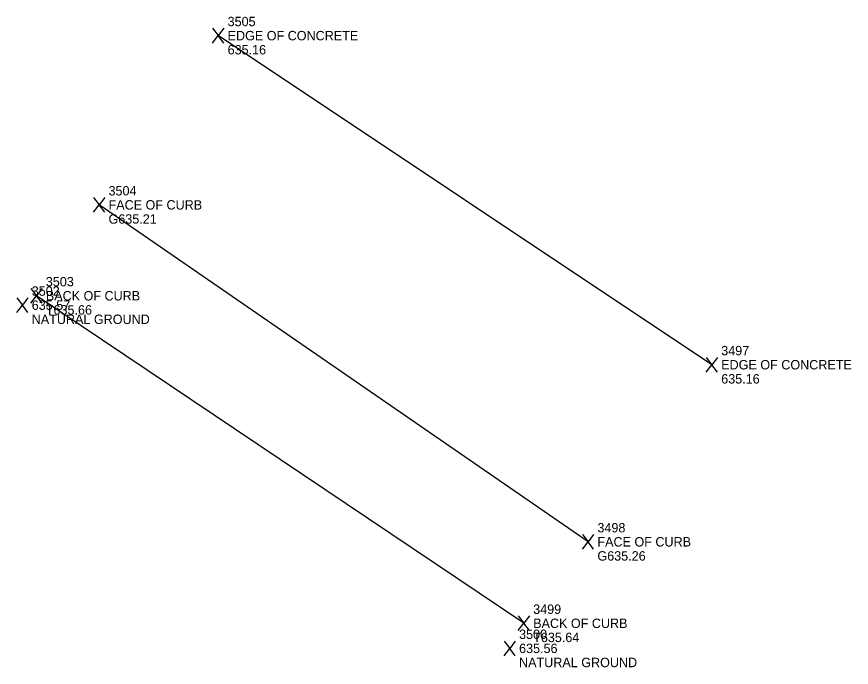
# Model space of a CAD drawing. Extents: x 2250985 to 2256614, y 13788366 to 13792478.
# Drawn here: x 2255030.8 to 2255036.13, y 13790711.88 to 13790716.03 of the extents above; entities that cross this region are included whole.
import ezdxf

# ---------------------------------------------------------------- set-up
doc = ezdxf.new("R2010")
doc.units = 0
for name, color, linetype in [('BORD_legend_drn_area', 7, 'Continuous'), ('BORD_legend_int', 7, 'Continuous'), ('BORD_legend_plan_prof_screen', 7, 'Continuous'), ('BORD_legend_TCP', 7, 'Continuous'), ('BORD_legend_TCP_screen', 7, 'Continuous'), ('BORD_notes_SAWS_sewer', 7, 'Continuous'), ('BORD_notes_SAWS_sewer_prof', 7, 'Continuous'), ('BORD_scale_plan_400', 7, 'Continuous'), ('BORD_scale_plan_profile_100_10', 7, 'Continuous'), ('BORD_scale_plan_profile_10_5', 7, 'Continuous'), ('BORD_scale_plan_profile_20_2', 7, 'Continuous'), ('BORD_scale_plan_profile_40_10', 7, 'Continuous'), ('BORD_seal_BA', 7, 'Continuous'), ('E_Road_Unpaved', 7, 'Continuous'), ('E_ROW_Driveway', 7, 'Continuous'), ('E_ROW_PropertyLine', 7, 'Continuous')]:
    doc.layers.add(name, color=color, linetype=linetype)

# ---------------------------------------------------------------- blocks, each defined once
blk = doc.blocks.new('EC')
at = {"layer": 'BORD_notes_SAWS_sewer'}
for p in [(-0.072, 0.094), (-0.072, -0.094), (0.072, 0.094), (0.072, -0.094)]:
    blk.add_line(p, (0, 0), dxfattribs=at)
blk = doc.blocks.new('CRB')
at = {"layer": 'BORD_scale_plan_400'}
for p in [(-0.072, 0.094), (-0.072, -0.094), (0.072, 0.094), (0.072, -0.094)]:
    blk.add_line(p, (0, 0), dxfattribs=at)
blk = doc.blocks.new('NG')
at = {"layer": 'BORD_legend_plan_prof_screen'}
for p in [(-0.072, 0.094), (-0.072, -0.094), (0.072, 0.094), (0.072, -0.094)]:
    blk.add_line(p, (0, 0), dxfattribs=at)
blk = doc.blocks.new('GUT')
at = {"layer": 'BORD_seal_BA'}
for p in [(-0.072, 0.094), (-0.072, -0.094), (0.072, 0.094), (0.072, -0.094)]:
    blk.add_line(p, (0, 0), dxfattribs=at)

msp = doc.modelspace()

# ---------------------------------------------------------------- linework, layer by layer
at = {"layer": 'BORD_seal_BA'}
for p in [(2255034.414, 13790712.727), (2255034.486, 13790712.727), (2255034.414, 13790712.633), (2255034.486, 13790712.633)]:
    msp.add_line(p, (2255034.45, 13790712.68), dxfattribs=at)
at = {"layer": 'E_Road_Unpaved'}
msp.add_line((2255034.04, 13790712.16), (2255030.93, 13790714.25), dxfattribs=at)
at = {"layer": 'E_ROW_Driveway'}
msp.add_line((2255035.24, 13790713.81), (2255032.09, 13790715.91), dxfattribs=at)
at = {"layer": 'E_ROW_PropertyLine'}
msp.add_line((2255034.45, 13790712.68), (2255031.33, 13790714.83), dxfattribs=at)

# ---------------------------------------------------------------- block references
at = {"layer": 'BORD_legend_plan_prof_screen', "xscale": 0.5, "yscale": 0.5}
for p in [(2255030.84, 13790714.19), (2255033.95, 13790712)]:
    msp.add_blockref('NG', p, dxfattribs=at)
at = {"layer": 'BORD_notes_SAWS_sewer', "xscale": 0.5, "yscale": 0.5}
for p in [(2255032.09, 13790715.91), (2255035.24, 13790713.81)]:
    msp.add_blockref('EC', p, dxfattribs=at)
at = {"layer": 'BORD_scale_plan_400', "xscale": 0.5, "yscale": 0.5}
for p in [(2255030.93, 13790714.25), (2255034.04, 13790712.16)]:
    msp.add_blockref('CRB', p, dxfattribs=at)
at = {"layer": 'BORD_seal_BA', "xscale": 0.5, "yscale": 0.5}
msp.add_blockref('GUT', (2255031.33, 13790714.83), dxfattribs=at)

# ---------------------------------------------------------------- texts
at = {"layer": 'BORD_legend_drn_area'}
for p in [(2255032.15, 13790715.88), (2255035.3, 13790713.78)]:
    msp.add_text('EDGE OF CONCRETE', height=0.06, dxfattribs=at).set_placement(p)
at = {"layer": 'BORD_legend_int'}
for p in [(2255030.9, 13790714.07), (2255034.01, 13790711.88)]:
    msp.add_text('NATURAL GROUND', height=0.06, dxfattribs=at).set_placement(p)
at = {"layer": 'BORD_legend_TCP'}
for s, p in [('3502', (2255030.9, 13790714.25)), ('3500', (2255034.01, 13790712.06))]:
    msp.add_text(s, height=0.06, dxfattribs=at).set_placement(p)
at = {"layer": 'BORD_legend_TCP_screen'}
for s, p in [('635.57', (2255030.9, 13790714.16)), ('635.56', (2255034.01, 13790711.97))]:
    msp.add_text(s, height=0.06, dxfattribs=at).set_placement(p)
at = {"layer": 'BORD_notes_SAWS_sewer'}
for p in [(2255032.15, 13790715.79), (2255035.3, 13790713.69)]:
    msp.add_text('635.16', height=0.06, dxfattribs=at).set_placement(p)
at = {"layer": 'BORD_notes_SAWS_sewer_prof'}
for s, p in [('3505', (2255032.15, 13790715.97)), ('3497', (2255035.3, 13790713.87))]:
    msp.add_text(s, height=0.06, dxfattribs=at).set_placement(p)
at = {"layer": 'BORD_scale_plan_400'}
for s, p in [('T635.66', (2255030.99, 13790714.13)), ('T635.64', (2255034.1, 13790712.04))]:
    msp.add_text(s, height=0.06, dxfattribs=at).set_placement(p)
at = {"layer": 'BORD_scale_plan_profile_100_10'}
for p in [(2255030.99, 13790714.22), (2255034.1, 13790712.13)]:
    msp.add_text('BACK OF CURB', height=0.06, dxfattribs=at).set_placement(p)
at = {"layer": 'BORD_scale_plan_profile_10_5'}
for s, p in [('3504', (2255031.39, 13790714.89)), ('3498', (2255034.51, 13790712.74))]:
    msp.add_text(s, height=0.06, dxfattribs=at).set_placement(p)
at = {"layer": 'BORD_scale_plan_profile_20_2'}
for p in [(2255031.39, 13790714.8), (2255034.51, 13790712.65)]:
    msp.add_text('FACE OF CURB', height=0.06, dxfattribs=at).set_placement(p)
at = {"layer": 'BORD_scale_plan_profile_40_10'}
for s, p in [('3503', (2255030.99, 13790714.31)), ('3499', (2255034.1, 13790712.22))]:
    msp.add_text(s, height=0.06, dxfattribs=at).set_placement(p)
at = {"layer": 'BORD_seal_BA'}
for s, p in [('G635.21', (2255031.39, 13790714.71)), ('G635.26', (2255034.51, 13790712.56))]:
    msp.add_text(s, height=0.06, dxfattribs=at).set_placement(p)

doc.saveas('drawing.dxf')
